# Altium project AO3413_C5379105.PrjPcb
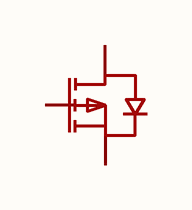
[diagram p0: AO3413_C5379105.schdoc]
1 sheet, 1 parts. Net scope: global (net labels, ports and power ports of the same name join across sheets).

## Sheet AO3413_C5379105.schdoc
size 127 x 101 mm

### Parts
Q?  ao3413_c5379105  [SOT-23-3_L2.9-W1.6-P1.90-LS2.8-BR]  (value not drawn)

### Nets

Not connected (* = marked no-connect by the designer): Q? 1(G) 2(S) 3(D)

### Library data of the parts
Q? = ao3413_c5379105: 数量:1个P沟道;漏源电压(Vdss):20V;连续漏极电流(Id):3A;导通电阻(RDS(on)):60mΩ@4.5V;耗散功率(Pd):1.56W;阈值电压(Vgs(th)):650mV;; Manufacturer: MSKSEMI(美森科); ManufacturerPart: AO3413; AddInBom: yes; ModelId: 89cb27a44ab2466697082bb9fd73a7d0; ModelName: SOT-23-3L_L2.9-W1.6-H1.1-LS2.8-P0.95; ModelTransform: 114.173,110.236,0,90,0,0,0,0,0; Number: 1个P沟道; Drain to Source Voltage: 20V; Current - Continuous Drain(Id): 3A; Pd - Power Dissipation: 1.56W; Gate Threshold Voltage (Vgs(th)): 650mV; Gate Charge(Qg): 4.8nC@4.5V; Input Capacitance(Ciss): 550pF; Reverse Transfer Capacitance (Crss@Vds): 55pF; Output Capacitance(Coss): 65pF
